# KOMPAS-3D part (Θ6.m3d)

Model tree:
1. Эскиз:1
2. Операция выдавливания:1
     Расстояние 1 = 2
3. Скругление:1
     Радиус = 2
4. Эскиз:2
5. Вырезать элемент выдавливания:1
     Расстояние 1 = 10
